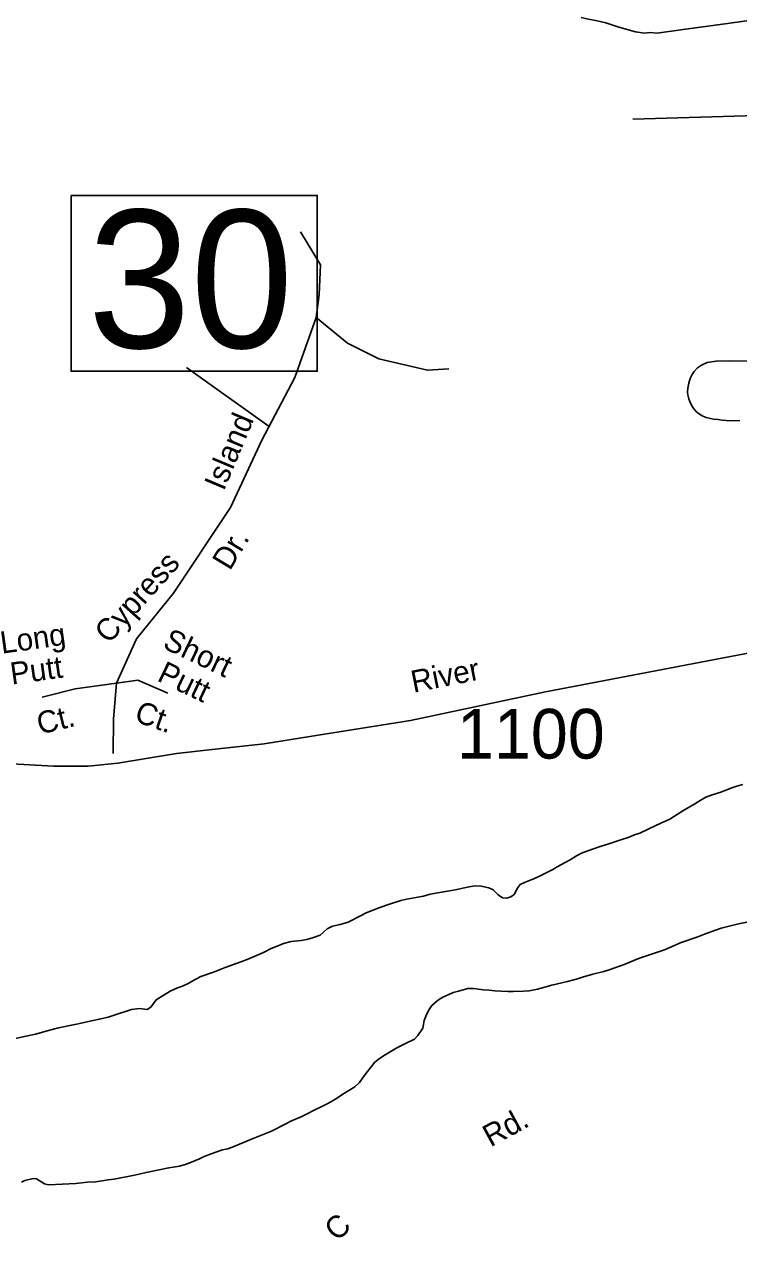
# Model space of a CAD drawing. Extents: x 1945482 to 2853149, y 66427 to 1015778.
# Drawn here: x 2329928 to 2332051, y 111496 to 115103 of the extents above; entities that cross this region are included whole.
import ezdxf

# ---------------------------------------------------------------- set-up
doc = ezdxf.new("R2010")
doc.units = 0
for name, color, linetype in [('Old_Level_10', 7, 'Continuous'), ('Old_Level_11', 7, 'Continuous'), ('Old_Level_31', 7, 'Continuous'), ('Old_Level_32', 7, 'Continuous'), ('Old_Level_35', 7, 'Continuous'), ('Old_Level_60', 7, 'Continuous'), ('Old_Level_8', 7, 'Continuous')]:
    doc.layers.add(name, color=color, linetype=linetype)

msp = doc.modelspace()

# ---------------------------------------------------------------- linework, layer by layer
at = {"layer": 'Old_Level_31'}
msp.add_lwpolyline([(2330067.3, 114594.5), (2330798.6, 114594.5), (2330798.6, 114071.9), (2330067.3, 114071.9)], close=True, dxfattribs=at)
at = {"layer": 'Old_Level_32'}
msp.add_lwpolyline([(2333049.4, 113479.8), (2333031.3, 113443.2), (2333011.6, 113419.9), (2332970.9, 113404.8), (2332724.3, 113355.8), (2332286.8, 113273.9), (2331476.7, 113118.6), (2331075.9, 113033.9), (2330776.7, 112985.9), (2330640.9, 112964.1), (2330495.5, 112948.9), (2330380.3, 112935.5), (2330206.5, 112906.5), (2330117.5, 112897.7), (2330014.6, 112897.7), (2329890.7, 112904.7)], dxfattribs=at)
at = {"layer": 'Old_Level_35'}
for points in [[(2331583.1, 115123.2), (2331600.1, 115119), (2331630.2, 115113.3), (2331656.4, 115107.7), (2331692.3, 115096), (2331726.5, 115086.2), (2331744.8, 115080.4), (2331758.6, 115078.6), (2331770.5, 115076.8), (2331788.5, 115079.2), (2331808.6, 115077.3), (2331886.6, 115088), (2332018.5, 115105.3), (2332166.3, 115126.9), (2332216.2, 115135.4), (2332282.1, 115138), (2332360, 115142.7), (2332490, 115142.3), (2332694.1, 115142.5), (2332984.1, 115139.5), (2333188.5, 115138.7)], [(2331736.3, 114821.6), (2332474.2, 114842.8), (2332826.2, 114855.6)], [(2330749, 114486.3), (2330808.3, 114388.7), (2330804.1, 114299.6), (2330795.6, 114231.7), (2330732, 114053.5), (2330634.5, 113866.7), (2330541.2, 113667.2), (2330371.5, 113412.6), (2330261.3, 113276.8), (2330201.9, 113145.2), (2330265.5, 113153.7), (2330354.6, 113115.5)], [(2330795.6, 114231.7), (2330888.9, 114155.3), (2330982.2, 114108.6), (2331126.4, 114074.7), (2331190, 114078.9)], [(2332683.1, 114091.8), (2332022.9, 114103.1), (2331983.9, 114101.6), (2331958.1, 114098.3), (2331941.1, 114090.4), (2331929.3, 114081.7), (2331918.8, 114070.8), (2331913.3, 114062), (2331907.2, 114050), (2331903.1, 114036.7), (2331899.8, 114022.1), (2331899.6, 114009.6), (2331900.2, 114002.1), (2331902.7, 113990.4), (2331906, 113981.7), (2331912, 113968.8), (2331918.3, 113959.8), (2331924.5, 113952.2), (2331934.7, 113944.1), (2331944.4, 113938.2), (2331954.4, 113934.3), (2331967.4, 113931.2), (2331976.9, 113929.6), (2331989.1, 113928.2), (2332002.7, 113926.7), (2332026.7, 113925), (2332054.9, 113925.5)], [(2330409.7, 114083.2), (2330655.7, 113907.3)], [(2330201.9, 113145.2), (2330078.9, 113128.3), (2329981.3, 113102.8)], [(2330201.9, 113145.2), (2330193.4, 113039.1), (2330192.6, 112936)]]:
    msp.add_lwpolyline(points, dxfattribs=at)
at = {"layer": 'Old_Level_60'}
for points in [[(2331214, 112531.8), (2331231, 112535.8), (2331250, 112539.6), (2331267.2, 112541.9), (2331285.5, 112541), (2331309.2, 112536.9), (2331321.2, 112530.5), (2331336.7, 112515.9), (2331349.5, 112506.9), (2331362, 112505.5), (2331374, 112509.3), (2331385, 112517.4), (2331392.7, 112534.5), (2331401.7, 112546), (2331414.5, 112552.1), (2331429.2, 112558.4), (2331444.5, 112563.8), (2331459.5, 112571.2), (2331472.7, 112578.2), (2331498.5, 112590.8), (2331512.2, 112598.8), (2331535.5, 112611.3), (2331550, 112619.7), (2331569.5, 112631.7), (2331584.5, 112639.9), (2331603, 112646.3), (2331622.5, 112653.7), (2331636.7, 112658.3), (2331665.5, 112666.8), (2331704.2, 112680.3), (2331723, 112686.4), (2331742, 112693.7), (2331757.7, 112699.2), (2331805.2, 112721.9), (2331820, 112728.7), (2331847, 112740.5), (2331885.7, 112765.3), (2331921, 112786.4), (2331936.5, 112796.3), (2331953.5, 112806.4), (2331972.7, 112813), (2331995.7, 112819.7), (2332033.5, 112834.8), (2332048.5, 112839.5), (2332063.5, 112843.1)], [(2329892, 112086.8), (2329961, 112101.9), (2330000, 112112.8), (2330030, 112120.1), (2330083.7, 112131), (2330132.7, 112141.7), (2330151.2, 112146.3), (2330177.2, 112152.2), (2330198, 112159.2), (2330246.5, 112174.3), (2330270.7, 112177.4), (2330293.2, 112174.5), (2330304.2, 112182), (2330320.2, 112203.2), (2330328, 112208.4), (2330361.2, 112229.4), (2330383, 112239.4), (2330398, 112244.2), (2330415, 112252.1), (2330437.5, 112265.2), (2330452.7, 112272.6), (2330490, 112286), (2330524.7, 112299.5), (2330574.7, 112317.6), (2330590.2, 112323.8), (2330639.2, 112344.2), (2330662.2, 112355.6), (2330684.5, 112364.9), (2330698.2, 112371.2), (2330721.2, 112376.7), (2330751, 112380.2), (2330768, 112383.3), (2330787.7, 112389.1), (2330807.2, 112396.2), (2330817.2, 112404.3), (2330828.7, 112414.8), (2330844, 112422.6), (2330866.7, 112427.3), (2330890.5, 112433.9), (2330929.7, 112454.6), (2330944, 112461.7), (2330985.2, 112478.4), (2331010.2, 112487.2), (2331046.7, 112498.9), (2331065.2, 112502.6), (2331097.5, 112508.2), (2331114.7, 112512.1), (2331134.5, 112517.1), (2331157.5, 112522), (2331197.5, 112528.4), (2331214, 112531.8)], [(2329919.5, 111661.6), (2329930, 111666.1), (2329954.7, 111672.8), (2329964.7, 111671.8), (2329987.7, 111656.3), (2330000, 111654), (2330081, 111657.4), (2330116, 111661.2), (2330139.7, 111662.8), (2330159.5, 111665.9), (2330177.5, 111668.3), (2330195, 111670.1), (2330256, 111682.4), (2330273, 111686), (2330290.2, 111690.3), (2330358, 111704.2), (2330389.2, 111709), (2330405.7, 111713.7), (2330420.5, 111719.3), (2330448.5, 111730.6), (2330462.2, 111737.9), (2330483.5, 111745.3), (2330497.5, 111750.9), (2330517.2, 111757.5), (2330533, 111760.6), (2330549, 111766.3), (2330598.5, 111787.7), (2330662.5, 111813.6), (2330705.5, 111834.9), (2330720.5, 111843), (2330752.5, 111856.8), (2330769.2, 111864.9), (2330787.7, 111874.9), (2330816.5, 111888.6), (2330832, 111896.6), (2330846, 111904.7), (2330861.7, 111914.4), (2330875, 111923.3), (2330910, 111944.9), (2330924, 111957.9), (2330935, 111973.8), (2330948.5, 111990.4), (2330970, 112018.2), (2330982.7, 112028.3), (2330996, 112036.7), (2331035.5, 112060.5), (2331063.2, 112074.8), (2331087.5, 112086.9), (2331098, 112097.9), (2331113, 112119.5), (2331117, 112141.9), (2331122, 112156.8), (2331129.2, 112171.8), (2331139.2, 112186.4), (2331158.7, 112203.6), (2331172, 112211.6), (2331187.5, 112218.6), (2331203, 112224.9), (2331218.5, 112229.7), (2331246.7, 112236.7), (2331262.7, 112237.3), (2331293, 112233.3), (2331310, 112231.8), (2331326.2, 112230.3), (2331345, 112229.1), (2331365.2, 112228.5), (2331381.5, 112228.3), (2331412, 112229), (2331428.5, 112230.3), (2331453.5, 112235.7), (2331495.5, 112247), (2331543, 112258.2), (2331572.5, 112265.8), (2331586.7, 112270.5), (2331617.7, 112279.9), (2331650.7, 112287.7), (2331666.2, 112292.9), (2331710.5, 112308.8), (2331756.2, 112327.4), (2331830.5, 112351.9), (2331846.2, 112359.4), (2331880, 112373.8), (2331929.5, 112390.7), (2331949.5, 112399), (2331971.2, 112407), (2331999, 112416.5), (2332015.5, 112420.9), (2332050.7, 112429), (2332110.5, 112441.2)]]:
    msp.add_lwpolyline(points, dxfattribs=at)

# ---------------------------------------------------------------- texts
at = {"layer": 'Old_Level_10'}
for s, rotation, p in [(' Island ', 67.1787, (2330511.5, 113691.3)), ('Dr.', 58.8391, (2330539, 113476.8)), ('Cypress', 48.1744, (2330179.7, 113259.1)), ('Long', 7.9521, (2329861.1, 113232.2)), ('Short', 334.4808, (2330336, 113250.8)), ('Putt', 7.9521, (2329890.9, 113140.3)), ('Putt', 334.4808, (2330319.6, 113153.2)), ('Ct.', 340.6434, (2330251.9, 113032.4)), ('Ct.', 13.7445, (2329974.4, 112991.6))]:
    msp.add_text(s, height=65.62, rotation=rotation, dxfattribs=at).set_placement(p)
at = {"layer": 'Old_Level_11'}
for s, height, rotation, p in [('River', 65.62, 11.2755, (2331084.5, 113116)), ('Rd.', 65.62, 28.6409, (2331313.8, 111764.6)), ('C', 65.6, 43.0253, (2330857.8, 111483.2))]:
    msp.add_text(s, height=height, rotation=rotation, dxfattribs=at).set_placement(p)
at = {"layer": 'Old_Level_31'}
msp.add_text('30', height=410.1, dxfattribs=at).set_placement((2330117.2, 114141.2))
at = {"layer": 'Old_Level_8'}
msp.add_text('1100', height=147.64, dxfattribs=at).set_placement((2331214, 112920.7))

doc.saveas('drawing.dxf')
